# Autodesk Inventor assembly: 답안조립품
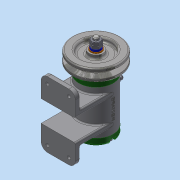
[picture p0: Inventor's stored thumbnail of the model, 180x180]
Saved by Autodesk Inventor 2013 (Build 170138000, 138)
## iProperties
Created: 2017-02
Part Number: 답안조립품
Document SubType Name: Assembly
Designer: dgall
Author: dgall
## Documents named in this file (16)
- C:\Users\dgall\Desktop\470207V1025\답안조립품.iam
- C:\Users\dgall\Desktop\470207V1025\본체.ipt
- C:\Users\dgall\Desktop\470207V1025\축.ipt
- C:\Users\dgall\Desktop\470207V1025\키 3 x 3 x 12.ipt
- C:\Users\dgall\Desktop\470207V1025\베어링 15 x 32 x 9.ipt
- C:\Users\dgall\Desktop\470207V1025\뒤커버.ipt
- C:\Users\dgall\Desktop\470207V1025\앞커버.ipt
- C:\Users\dgall\Desktop\470207V1025\오일 실 15 25 7.ipt
- C:\Users\dgall\Desktop\470207V1025\볼트 M4 x 12.ipt
- C:\Users\dgall\Desktop\470207V1025\V벨트풀리.ipt
- C:\Users\dgall\Desktop\470207V1025\너트 M 8.ipt
- C:\Users\dgall\Desktop\470207V1025\스프링와셔 8.ipt
- C:\Users\dgall\Desktop\470207V1025\와셔 8x17.ipt
- C:\Users\dgall\Desktop\470207V1025\니플 M 6 x 0.75.ipt
- C:\Users\dgall\Desktop\470207V1025\볼트 M 6 x 8.ipt
- C:\Users\dgall\Desktop\470207V1025\와셔 6x11.5.ipt
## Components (11 placed, 3 different names)
1. KS B 2023 6002 - 15 x 32 x 9:1
2. KS B 2023 6002 - 15 x 32 x 9:2
3. V벨트풀리:1
4. ISO 4762 M4 x 12:2
5. ISO 4762 M4 x 12:3
6. ISO 4762 M4 x 12:4
7. ISO 4762 M4 x 12:5
8. ISO 4762 M4 x 12:1
9. ISO 4762 M4 x 12:6
10. ISO 4762 M4 x 12:7
11. ISO 4762 M4 x 12:8
